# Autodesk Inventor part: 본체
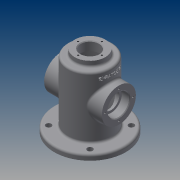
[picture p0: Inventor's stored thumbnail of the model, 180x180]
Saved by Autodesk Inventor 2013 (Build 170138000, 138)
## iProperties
Created: 2014-12
Part Number: 본체
Material: Generic
Document SubType Name: Modeling
Designer: CAD-B28
Density: 1 g/cm^3
Author: CAD-B28
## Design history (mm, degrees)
sketch "스케치1"
  geometry: C1 r 32.5 at (0, 0); 1 further point
  constraints: 1 centre point, 1 coincident
  dimensions: "d0" = 65 diameter of C1
extrude "돌출1" new body sketch "스케치1" distance "d1" = 43; taper "d3" = 0 deg; dims "d2" = 55, "d4" = 0
sketch "스케치2"
  geometry: C1 r 32.5 at (0, 0) reference; C2 r 52.5 at (0, 0)
  constraints: 1 centre point, 1 coincident
  dimensions: "d5" = 105 diameter of C2
extrude "돌출2" join sketch "스케치2" distance "d6" = 8; taper "d7" = 0 deg
sketch "스케치3"
  geometry: C1 r 52.5 at (0, 0) reference; C2 r 27.5 at (0, 0)
  constraints: 1 centre point, 1 coincident
  dimensions: "d8" = 55 diameter of C2
extrude "돌출3" cut sketch "스케치3" distance "d9" = 93; taper "d10" = 0 deg
sketch "스케치4"
  geometry: L1 (-42.5, 0)-(54.519, 0) reference; L2 (-42.5, 0)-(-42.5, 25); L3 (-42.5, 25)-(42.5, 25); L4 (42.5, 25)-(42.5, 0); L5 (-32.5, -47)-(-32.5, 43) reference; L6 (32.5, -47)-(32.5, 43) reference; 1 further point
  constraints: 8 end point, 3 perpendicular, 2 horizontal, 1 point on line
  dimensions: "d11" = 50 diameter of L3 L1; "d13" = 10 distance between parallel lines of L5 L2; "d14" = 10 distance between parallel lines of L4 L6
revolve "회전1" sketch "스케치4" stored, may be unused: angle "d15" = 90 deg
sketch "스케치5"
  geometry: L1 (-42.66, 0)-(42.5, 0) reference; L2 (-42.66, 0)-(-42.66, 16); L3 (-42.66, 16)-(-30.66, 16); L4 (-30.66, 16)-(-30.66, 12.5); L5 (-30.66, 12.5)-(30.5, 12.5); L6 (30.5, 12.5)-(30.5, 16); L7 (30.5, 16)-(42.5, 16); L8 (42.5, 16)-(42.5, 0); L9 (42.5, -25)-(42.5, 25) reference; 2 further points
  constraints: 16 end point, 4 parallel, 2 horizontal, 2 perpendicular, 1 collinear, 1 midpoint, 1 point on line
  dimensions: "d16" = 12 distance of L2.end L3.end; "d18" = 12 distance of L6.end L7.end; "d19" = 32 diameter of L7 L1; "d21" = 32 diameter of L3 L1; "d22" = 25 diameter of L5 L1
revolve "회전2" sketch "스케치5" stored, may be unused: angle "d23" = 90 deg
extrude "돌출4" cut sketch "스케치3" distance "d24" = 93; taper "d25" = 0 deg
sketch "스케치6"
  geometry: C1 r 32.5 at (0, 0) reference; C2 r 22.5 at (0, 0)
  constraints: 1 centre point, 1 coincident
  dimensions: "d26" = 45 diameter of C2
extrude "돌출5" join sketch "스케치6" distance "d27" = 8; taper "d28" = 0 deg
sketch "스케치7"
  geometry: C1 r 22.5 at (0, 0) reference; C2 r 13.5 at (0, 0)
  constraints: 1 centre point, 1 coincident
  dimensions: "d29" = 27 diameter of C2
extrude "돌출6" cut sketch "스케치7" stored distance "d30" = 8; taper "d31" = 0 deg
sketch "스케치8" dims "d32" = 41
  geometry: L1 (0, 0)-(25, 0); 2 further points
  constraints: 2 end point, 2 horizontal alignment, 1 coincident, 1 horizontal, 1 point on line, 3 other
hole "구멍1" sketch "스케치8" at (20.5, 0) diameter "d33" = 2.459; stored, may be unused: countersink angle "d37" = 90 deg, drill point angle "d39" = 118 deg; dims "d34" = 6, "d35" = 4, "d36" = 2, "d38" = 8
sketch "스케치9" dims "d43" = 35
  geometry: L1 (0, 0)-(0, 20.281); C1 r 22.5 at (0, 0) reference; 1 further point
  constraints: 2 end point, 1 coincident, 1 point on line, 1 vertical, 1 vertical alignment, 2 other
hole "구멍2" sketch "스케치9" at (0, 17.5) diameter "d44" = 2.459; stored, may be unused: countersink angle "d48" = 90 deg, drill point angle "d50" = 118 deg; dims "d45" = 6, "d46" = 4, "d47" = 2, "d49" = 8
chamfer "모따기1" distance "d54" = 1; stored, may be unused: second distance "d55" = 2, angle "d56" = 45 deg
fillet "모깎기1" dims "d57" = 0.3
sketch "스케치10" dims "d58" = 86
  geometry: L1 (0, 0)-(0, 50.353); L2 (0, 0)-(35.191, 35.191); C1 r 52.5 at (0, 0) reference; C2 r 4 at (30.406, 30.406)
  constraints: 4 end point, 1 centre point, 1 coincident, 1 point on line, 1 vertical, 3 other
  dimensions: "d59" = 45 deg angle of L2 L1; "d61" = 8 diameter of C2
extrude "돌출7" cut sketch "스케치10" stored distance "d62" = 8; taper "d63" = 0 deg
fillet "모깎기2" dims "d67" = 3
node "작업 평면1"
sketch "스케치11"
  geometry: L1 (0, 38.927)-(0, 28.211); L2 (-29.5, 43)-(29.5, 43) reference; 2 further points
  constraints: 2 end point, 1 point on line, 1 vertical, 1 other
  dimensions: "d69" = 9 distance from line of L2 point (0, 34)
feature "엠보싱1" sketch "스케치11" dims "d11" = 50, "d70" = 1, "d71" = 0
fillet "모깎기3" dims "d72" = 3
node "솔리드1"
pattern_circular "원형 패턴1" dims angle "d41" = 360 deg
mirror "대칭1"
pattern_circular "원형 패턴2" dims angle "d52" = 360 deg
pattern_circular "원형 패턴3" dims angle "d65" = 360 deg
other parameters: "d68" = 35.75
